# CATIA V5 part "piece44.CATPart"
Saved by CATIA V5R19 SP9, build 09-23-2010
Part number: vilebrequin 2
Bounding box of the stored display mesh (mm): x -57.798 to 68.193, y -31.64 to 31.64, z -31.64 to 31.64
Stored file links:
  Y:\projet be 2011-12\Etude cinématique\piece44.CATPart
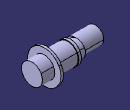
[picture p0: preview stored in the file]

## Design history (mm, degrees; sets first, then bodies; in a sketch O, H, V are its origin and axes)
Body1 (main body)
  DatumSurface1 to DatumSurface3
  Plane1: stored without definition
  DatumSurface4
  DatumCurve1 to DatumCurve3
  Sketch1 on Plane1, origin (0, 0, 0), H (1, 0, 0), V (0, 1, 0)
    line L1 (-17.7977, 16) -> (-5.1929, 16)
    line L2 (-5.1929, 16) -> (-5.1929, 21.0978)
    line L3 (-5.1929, 21.0978) -> (0, 21.0978)
    line L4 (0, 21.0978) -> (0, 20)
    line L5 (0, 20) -> (40, 20)
    line L6 (40, 20) -> (40, 31.6817)
    line L7 (40, 31.6817) -> (44.546, 31.6817)
    line L8 (44.546, 31.6817) -> (44.546, 20)
    point P9 (44.546, 20)
    line L9 (44.546, 20) -> (68.1927, 20)
    line L10 (68.1927, 20) -> (68.1927, 0)
    point P11 (68.1927, 0)
    line L11 (-17.7977, 16) -> (-17.7977, 0)
    point P12 (-17.7977, 0)
    reference projected line E1 through (0, 0) direction (1, 0) from edge of DatumCurve1
    reference projected line E2 (0, 40) -> (0, -40) from edge of DatumCurve2
    reference projected line E3 (40, 40) -> (40, -40) from edge of DatumCurve3
    distance E1 L5 = 20
    distance H L1 = 16
    horizontal: L1 H, L3 H, L5 H
    vertical: L2 V, L8 V, L10 V, L11 V
    parallelism: L4 L2, L6 L4, L7 L3, L9 L5
    coincidence: P9 L5, P11 H, P12 H, L4 E2, L6 E3
  Shaft1: profile Sketch1, axis Sketch1.H, angle 360
  Sketch2 on face of Shaft1 from Sketch1.L11, origin (-17.7977, 0, 0), H (0, -1, 0), V (0, 0, 1)
    circle A1 centre (4.965, -0.5904) radius 16
    point P1 (4.965, -0.5904)
    distance P1 O = 5
    radius A1 = 16
  Pad1: profile Sketch2, direction (-1, 0, 0), length 40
